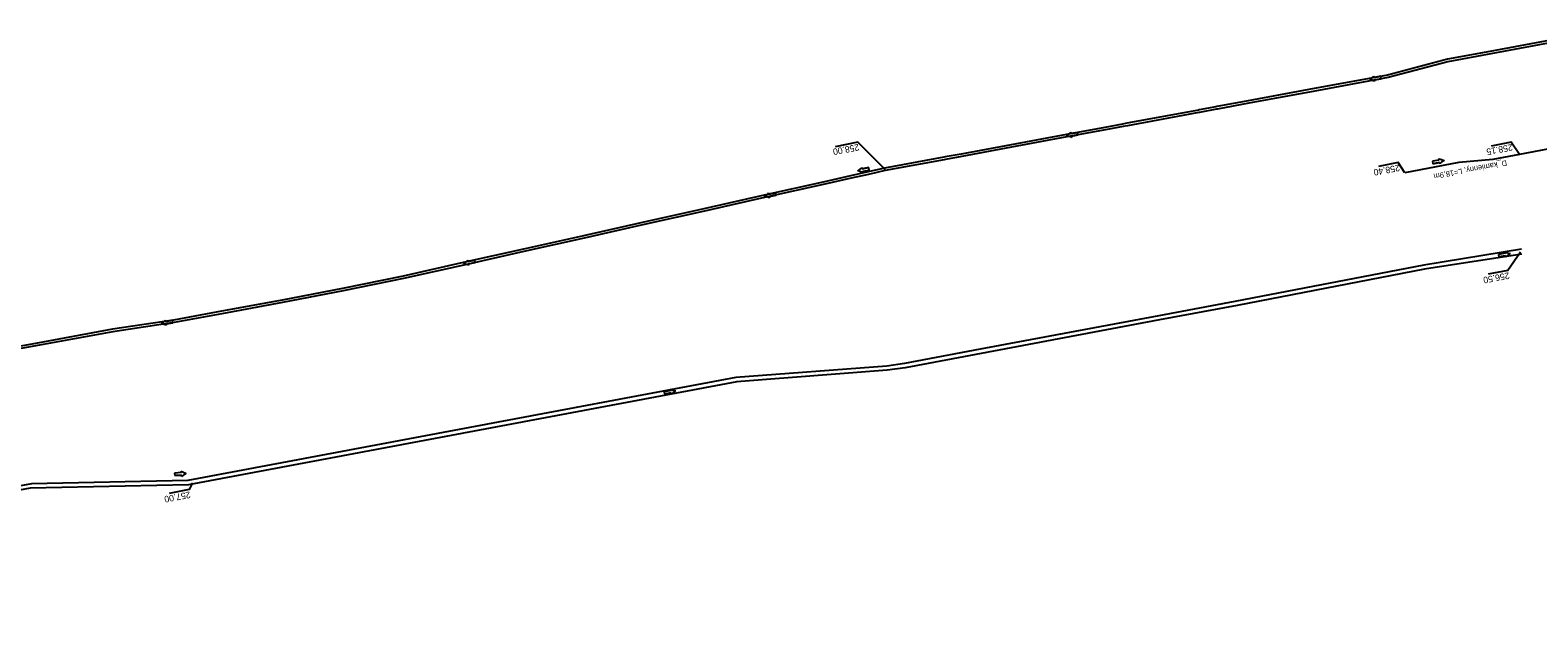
# Model space of a CAD drawing. Extents: x -1 to 65640748, y -22 to 5530284.
# Drawn here: x 6564923.1 to 6565167.7, y 5530057.8 to 5530154.6 of the extents above; entities that cross this region are included whole.
import ezdxf

# ---------------------------------------------------------------- set-up
doc = ezdxf.new("R2010")
doc.units = 0
for name, color, linetype in [('TOR_PS_ODW-drenaze', 7, 'Continuous'), ('TOR_PS_OPIS_O-opisy rurociagow', 7, 'Continuous'), ('TOR_PS_OPIS_T-INFO', 7, 'Continuous'), ('TOR_PS_T-rowy otwarte umocnione', 7, 'Continuous')]:
    doc.layers.add(name, color=color, linetype=linetype)

msp = doc.modelspace()

# ---------------------------------------------------------------- linework, layer by layer
at = {"layer": 'TOR_PS_ODW-drenaze'}
for points in [[(6565191.96, 5530139.54), (6565164.7, 5530134.37)], [(6565164.7, 5530134.37), (6565160.37, 5530133.55), (6565154.85, 5530133.06), (6565146.08, 5530131.4)]]:
    msp.add_lwpolyline(points, dxfattribs=at)
at = {"layer": 'TOR_PS_OPIS_O-opisy rurociagow'}
for p, q in [((6565142.19, 5530147.07), (6565141.11, 5530146.87)), ((6565141.11, 5530146.87), (6565142.19, 5530147.07)), ((6565141.18, 5530146.47), (6565142.26, 5530146.67)), ((6565141.18, 5530146.47), (6565142.26, 5530146.67)), ((6565142.26, 5530146.67), (6565142.19, 5530147.07)), ((6565142.26, 5530146.67), (6565142.19, 5530147.07)), ((6565093.02, 5530137.95), (6565091.95, 5530137.75)), ((6565091.95, 5530137.75), (6565093.02, 5530137.95)), ((6565092.02, 5530137.35), (6565093.1, 5530137.55)), ((6565092.02, 5530137.35), (6565093.1, 5530137.55)), ((6565093.1, 5530137.55), (6565093.02, 5530137.95)), ((6565093.1, 5530137.55), (6565093.02, 5530137.95)), ((6565151.65, 5530133.46), (6565150.58, 5530133.26)), ((6565151.65, 5530133.46), (6565150.58, 5530133.26)), ((6565150.58, 5530133.26), (6565150.65, 5530132.87)), ((6565150.58, 5530133.26), (6565150.65, 5530132.87)), ((6565150.65, 5530132.87), (6565151.73, 5530133.07)), ((6565151.73, 5530133.07), (6565150.65, 5530132.87)), ((6565059.15, 5530132.23), (6565058.07, 5530132.03)), ((6565058.07, 5530132.03), (6565059.15, 5530132.23)), ((6565058.15, 5530131.64), (6565059.22, 5530131.84)), ((6565058.15, 5530131.64), (6565059.22, 5530131.84)), ((6565059.22, 5530131.84), (6565059.15, 5530132.23)), ((6565059.22, 5530131.84), (6565059.15, 5530132.23)), ((6565044, 5530128.16), (6565042.93, 5530127.92)), ((6565042.93, 5530127.92), (6565044, 5530128.16)), ((6565043.02, 5530127.53), (6565044.09, 5530127.77)), ((6565043.02, 5530127.53), (6565044.09, 5530127.77)), ((6565044.09, 5530127.77), (6565044, 5530128.16)), ((6565044.09, 5530127.77), (6565044, 5530128.16)), ((6565162.36, 5530118.33), (6565161.29, 5530118.12)), ((6565162.36, 5530118.33), (6565161.29, 5530118.12)), ((6565161.29, 5530118.12), (6565161.36, 5530117.73)), ((6565161.29, 5530118.12), (6565161.36, 5530117.73)), ((6565161.36, 5530117.73), (6565162.43, 5530117.93)), ((6565162.43, 5530117.93), (6565161.36, 5530117.73)), ((6564995.21, 5530117.22), (6564994.15, 5530116.98)), ((6564994.15, 5530116.98), (6564995.21, 5530117.22)), ((6564994.23, 5530116.59), (6564995.3, 5530116.83)), ((6564994.23, 5530116.59), (6564995.3, 5530116.83)), ((6564995.3, 5530116.83), (6564995.21, 5530117.22)), ((6564995.3, 5530116.83), (6564995.21, 5530117.22)), ((6564946.18, 5530107.44), (6564945.11, 5530107.24)), ((6564945.11, 5530107.24), (6564946.18, 5530107.44)), ((6564945.18, 5530106.85), (6564946.26, 5530107.04)), ((6564945.18, 5530106.85), (6564946.26, 5530107.04)), ((6564946.26, 5530107.04), (6564946.18, 5530107.44)), ((6564946.26, 5530107.04), (6564946.18, 5530107.44)), ((6565027.01, 5530096.06), (6565025.94, 5530095.85)), ((6565027.01, 5530096.06), (6565025.94, 5530095.85)), ((6565025.94, 5530095.85), (6565026.01, 5530095.46)), ((6565025.94, 5530095.85), (6565026.01, 5530095.46)), ((6565026.01, 5530095.46), (6565027.09, 5530095.66)), ((6565027.09, 5530095.66), (6565026.01, 5530095.46)), ((6564947.64, 5530082.72), (6564946.55, 5530082.64)), ((6564947.64, 5530082.72), (6564946.55, 5530082.64)), ((6564946.55, 5530082.64), (6564946.58, 5530082.24)), ((6564946.55, 5530082.64), (6564946.58, 5530082.24)), ((6564946.58, 5530082.24), (6564947.67, 5530082.32)), ((6564947.67, 5530082.32), (6564946.58, 5530082.24))]:
    msp.add_line(p, q, dxfattribs=at)
for points in [[(6565141.08, 5530147.09), (6565141.08, 5530147.09)], [(6565141.24, 5530146.25), (6565141.24, 5530146.25)], [(6565091.92, 5530137.97), (6565091.92, 5530137.97)], [(6565092.07, 5530137.13), (6565092.07, 5530137.13)], [(6565151.6, 5530133.68), (6565151.6, 5530133.68)], [(6565151.76, 5530132.85), (6565151.76, 5530132.85)], [(6565058.04, 5530132.25), (6565058.04, 5530132.25)], [(6565058.2, 5530131.42), (6565058.2, 5530131.42)], [(6565042.89, 5530128.15), (6565042.89, 5530128.15)], [(6565043.08, 5530127.32), (6565043.08, 5530127.32)], [(6565162.31, 5530118.55), (6565162.31, 5530118.55)], [(6564994.11, 5530117.2), (6564994.11, 5530117.2)], [(6564994.29, 5530116.37), (6564994.29, 5530116.37)], [(6565162.47, 5530117.71), (6565162.47, 5530117.71)], [(6564945.08, 5530107.46), (6564945.08, 5530107.46)], [(6564945.23, 5530106.63), (6564945.23, 5530106.63)], [(6565026.96, 5530096.28), (6565026.96, 5530096.28)], [(6565027.12, 5530095.44), (6565027.12, 5530095.44)], [(6564947.61, 5530082.94), (6564947.61, 5530082.94)], [(6564947.67, 5530082.09), (6564947.67, 5530082.09)]]:
    msp.add_lwpolyline(points, dxfattribs=at)
for centre, radius, start, end in [((6565137.65, 5530150.61), 4.92, 303.8379, 314.2197), ((6565137.65, 5530150.61), 4.92, 303.8379, 314.2197), ((6565139.3, 5530141.73), 4.92, 66.8, 77.1818), ((6565139.3, 5530141.73), 4.92, 66.8, 77.1818), ((6565140.66, 5530146.92), 0.458, 353.6439, 22.1051), ((6565140.66, 5530146.92), 0.458, 353.6439, 22.1051), ((6565140.78, 5530146.26), 0.458, 358.9146, 27.3758), ((6565140.78, 5530146.26), 0.458, 358.9146, 27.3758), ((6565088.49, 5530141.49), 4.92, 303.8368, 314.2187), ((6565088.49, 5530141.49), 4.92, 303.8368, 314.2187), ((6565091.5, 5530137.8), 0.458, 353.6429, 22.1041), ((6565091.5, 5530137.8), 0.458, 353.6429, 22.1041), ((6565090.14, 5530132.61), 4.92, 66.7989, 77.1808), ((6565090.14, 5530132.61), 4.92, 66.7989, 77.1808), ((6565091.62, 5530137.14), 0.458, 358.9135, 27.3747), ((6565091.62, 5530137.14), 0.458, 358.9135, 27.3747), ((6565153.52, 5530138.21), 4.92, 247.0234, 257.4052), ((6565152.06, 5530133.68), 0.458, 179.1379, 207.5992), ((6565153.52, 5530138.21), 4.92, 247.0234, 257.4052), ((6565152.06, 5530133.68), 0.458, 179.1379, 207.5992), ((6565152.18, 5530133.02), 0.458, 173.8673, 202.3285), ((6565152.18, 5530133.02), 0.458, 173.8673, 202.3285), ((6565155.2, 5530129.34), 4.92, 124.0613, 134.4431), ((6565155.2, 5530129.34), 4.92, 124.0613, 134.4431), ((6565054.6, 5530135.76), 4.92, 304.0613, 314.4431), ((6565054.6, 5530135.76), 4.92, 304.0613, 314.4431), ((6565056.28, 5530126.89), 4.92, 67.0234, 77.4052), ((6565056.28, 5530126.89), 4.92, 67.0234, 77.4052), ((6565057.62, 5530132.08), 0.458, 353.8673, 22.3285), ((6565057.62, 5530132.08), 0.458, 353.8673, 22.3285), ((6565057.74, 5530131.42), 0.458, 359.1379, 27.5992), ((6565057.74, 5530131.42), 0.458, 359.1379, 27.5992), ((6565039.34, 5530131.54), 4.92, 305.9711, 316.353), ((6565039.34, 5530131.54), 4.92, 305.9711, 316.353), ((6565042.48, 5530127.96), 0.458, 355.7772, 24.2384), ((6565042.48, 5530127.96), 0.458, 355.7772, 24.2384), ((6565041.31, 5530122.73), 4.92, 68.9332, 79.3151), ((6565041.31, 5530122.73), 4.92, 68.9332, 79.3151), ((6565042.62, 5530127.31), 0.458, 1.0478, 29.509), ((6565042.62, 5530127.31), 0.458, 1.0478, 29.509), ((6565164.23, 5530123.07), 4.92, 247.0234, 257.4052), ((6565162.77, 5530118.54), 0.458, 179.138, 207.5992), ((6565164.23, 5530123.07), 4.92, 247.0234, 257.4052), ((6565162.77, 5530118.54), 0.458, 179.138, 207.5992), ((6565162.89, 5530117.89), 0.458, 173.8673, 202.3285), ((6565162.89, 5530117.89), 0.458, 173.8673, 202.3285), ((6565165.91, 5530114.2), 4.92, 124.0613, 134.4431), ((6565165.91, 5530114.2), 4.92, 124.0613, 134.4431), ((6564990.55, 5530120.6), 4.92, 305.9711, 316.353), ((6564990.55, 5530120.6), 4.92, 305.9711, 316.353), ((6564992.52, 5530111.78), 4.92, 68.9332, 79.3151), ((6564992.52, 5530111.78), 4.92, 68.9332, 79.3151), ((6564993.69, 5530117.01), 0.458, 355.7772, 24.2384), ((6564993.69, 5530117.01), 0.458, 355.7772, 24.2384), ((6564993.83, 5530116.36), 0.458, 1.0478, 29.509), ((6564993.83, 5530116.36), 0.458, 1.0478, 29.509), ((6564941.65, 5530110.99), 4.92, 303.7354, 314.1172), ((6564941.65, 5530110.99), 4.92, 303.7354, 314.1172), ((6564943.29, 5530102.11), 4.92, 66.6975, 77.0793), ((6564943.29, 5530102.11), 4.92, 66.6975, 77.0793), ((6564944.65, 5530107.29), 0.458, 353.5414, 22.0026), ((6564944.65, 5530107.29), 0.458, 353.5414, 22.0026), ((6564944.77, 5530106.64), 0.458, 358.812, 27.2733), ((6564944.77, 5530106.64), 0.458, 358.812, 27.2733), ((6565028.88, 5530100.8), 4.92, 247.0234, 257.4052), ((6565027.42, 5530096.27), 0.458, 179.138, 207.5992), ((6565028.88, 5530100.8), 4.92, 247.0234, 257.4052), ((6565027.42, 5530096.27), 0.458, 179.138, 207.5992), ((6565030.56, 5530091.93), 4.92, 124.0613, 134.4431), ((6565030.56, 5530091.93), 4.92, 124.0613, 134.4431), ((6565027.54, 5530095.61), 0.458, 173.8673, 202.3285), ((6565027.54, 5530095.61), 0.458, 173.8673, 202.3285), ((6564948.06, 5530082.88), 0.458, 172.6573, 201.1185), ((6564948.06, 5530082.88), 0.458, 172.6573, 201.1185), ((6564950.03, 5530087.22), 4.92, 240.5427, 250.9245), ((6564950.03, 5530087.22), 4.92, 240.5427, 250.9245), ((6564948.11, 5530082.22), 0.458, 167.3866, 195.8479), ((6564948.11, 5530082.22), 0.458, 167.3866, 195.8479), ((6564950.7, 5530078.22), 4.92, 117.5806, 127.9624), ((6564950.7, 5530078.22), 4.92, 117.5806, 127.9624)]:
    msp.add_arc(centre, radius, start, end, dxfattribs=at)
at = {"layer": 'TOR_PS_OPIS_T-INFO'}
for points in [[(6565061.79, 5530131.94), (6565057.34, 5530136.38), (6565053.68, 5530135.62)], [(6565164.7, 5530134.37), (6565163.33, 5530136.36), (6565160.1, 5530135.74)], [(6565146.08, 5530131.4), (6565145.03, 5530133.04), (6565141.8, 5530132.42)], [(6565164.87, 5530118.5), (6565162.82, 5530115.54), (6565159.59, 5530114.91)], [(6564949.43, 5530081.04), (6564948.88, 5530079.96), (6564945.65, 5530079.34)]]:
    msp.add_lwpolyline(points, dxfattribs=at)
at = {"layer": 'TOR_PS_T-rowy otwarte umocnione'}
for points in [[(6565178.56, 5530154.56), (6565169.71, 5530152.92), (6565159.88, 5530151.09), (6565153, 5530149.82), (6565143.28, 5530147.27)], [(6565178.64, 5530154.16), (6565153.07, 5530149.42), (6565143.38, 5530146.88)], [(6565143.28, 5530147.27), (6565130.52, 5530144.9), (6565120.69, 5530143.08), (6565115.61, 5530142.14), (6565115.45, 5530142.11), (6565112.71, 5530141.6), (6565112.6, 5530141.58), (6565110.86, 5530141.25), (6565101.02, 5530139.43), (6565100.31, 5530139.3), (6565097.45, 5530138.77), (6565091.19, 5530137.61), (6565081.36, 5530135.78), (6565074.15, 5530134.44), (6565071.53, 5530133.96), (6565071.3, 5530133.92), (6565061.69, 5530132.13), (6565059.03, 5530131.53), (6565056.2, 5530130.9), (6565051.93, 5530129.94), (6565042.17, 5530127.75), (6565032.41, 5530125.56), (6565022.64, 5530123.37), (6565012.88, 5530121.18), (6565003.12, 5530118.99), (6564993.35, 5530116.8), (6564983.59, 5530114.61), (6564973.79, 5530112.62), (6564963.98, 5530110.71), (6564954.14, 5530108.9), (6564946.37, 5530107.47), (6564936.47, 5530105.98), (6564924.57, 5530103.8), (6564919.16, 5530102.81)], [(6565143.38, 5530146.88), (6565130.6, 5530144.51), (6565120.76, 5530142.68), (6565115.68, 5530141.74), (6565115.52, 5530141.71), (6565112.78, 5530141.2), (6565112.67, 5530141.18), (6565110.93, 5530140.86), (6565101.1, 5530139.04), (6565100.38, 5530138.9), (6565097.53, 5530138.37), (6565091.27, 5530137.21), (6565081.43, 5530135.39), (6565074.23, 5530134.05), (6565071.6, 5530133.56), (6565071.38, 5530133.52), (6565061.77, 5530131.74), (6565059.1, 5530131.14), (6565056.27, 5530130.51), (6565052.01, 5530129.55), (6565042.24, 5530127.36), (6565032.48, 5530125.17), (6565022.72, 5530122.98), (6565012.95, 5530120.79), (6565003.19, 5530118.6), (6564993.43, 5530116.41), (6564983.67, 5530114.22), (6564973.87, 5530112.22), (6564964.05, 5530110.31), (6564954.21, 5530108.51), (6564946.46, 5530107.08), (6564936.55, 5530105.59), (6564924.65, 5530103.41), (6564919.24, 5530102.41)], [(6565165.02, 5530118.99), (6565149.15, 5530116.41), (6565118.49, 5530110.5), (6565106.2, 5530108.19), (6565077.21, 5530102.74), (6565064.93, 5530100.42), (6565062.05, 5530100.02), (6565037.6, 5530098.15), (6564948.68, 5530081.41), (6564923.31, 5530080.91)], [(6565165.08, 5530118.19), (6565149.28, 5530115.72), (6565118.9, 5530109.87), (6565106.32, 5530107.5), (6565077.36, 5530102.05), (6565065.04, 5530099.73), (6565062.13, 5530099.32), (6565037.68, 5530097.45)], [(6565037.71, 5530097.45), (6564948.79, 5530080.72), (6564923.11, 5530080.21)], [(6564923.11, 5530080.21), (6564810.89, 5530059.18), (6564804.11, 5530057.91), (6564802.28, 5530057.82)], [(6564923.31, 5530080.91), (6564918.89, 5530080.08), (6564909.06, 5530078.24), (6564899.23, 5530076.4), (6564889.4, 5530074.56), (6564879.57, 5530072.71), (6564869.75, 5530070.87), (6564859.92, 5530069.03), (6564850.09, 5530067.19), (6564840.26, 5530065.35), (6564830.43, 5530063.5), (6564820.6, 5530061.66), (6564810.77, 5530059.82), (6564803.39, 5530058.44)]]:
    msp.add_lwpolyline(points, dxfattribs=at)

# ---------------------------------------------------------------- texts
at = {"layer": 'TOR_PS_OPIS_O-opisy rurociagow'}
msp.add_text('D_kamienny, L=18,9m', height=0.9, rotation=190.5985, dxfattribs=at).set_placement((6565162.56, 5530133.44))
at = {"layer": 'TOR_PS_OPIS_T-INFO'}
for s, p in [('258.00', (6565057.47, 5530136.08)), ('258.15', (6565163.47, 5530136.07)), ('258.40', (6565145.16, 5530132.74)), ('256.50', (6565162.95, 5530115.24)), ('257.00', (6564949.01, 5530079.66))]:
    msp.add_text(s, height=1.05, rotation=190.7159, dxfattribs=at).set_placement(p)

doc.saveas('drawing.dxf')
